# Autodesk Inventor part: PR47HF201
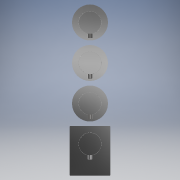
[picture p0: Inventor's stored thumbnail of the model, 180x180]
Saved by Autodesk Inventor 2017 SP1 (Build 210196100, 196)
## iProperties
Created: 2018-11
Part Number: PR47HF201
Material: Generico
Document SubType Name: Modeling
Designer: CIANI A.
Density: 1 g/cm^3
Appearance: Default
Author: CIANI A.
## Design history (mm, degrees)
feature "Base4"
node "Solido1"
node "Solido5"
